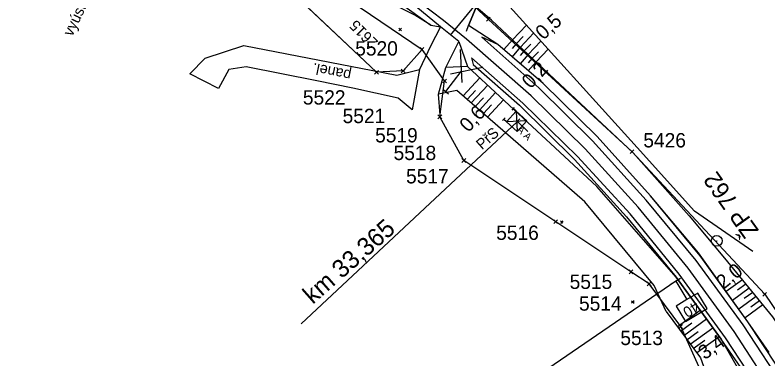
# Model space of a CAD drawing. Extents: x -805011 to -803920, y -1150790 to -1150234.
# Drawn here: x -804282.8 to -804177.7, y -1150562.3 to -1150514.3 of the extents above; entities that cross this region are included whole.
import ezdxf

# ---------------------------------------------------------------- set-up
doc = ezdxf.new("R2010")
doc.units = 0
for name, color, linetype in [('0381KM032-037P - Vrstva 1', 7, 'Continuous'), ('0381KM032-037P - Vrstva 4', 7, 'Continuous'), ('0381KM032-037P - Vrstva 43', 7, 'Continuous'), ('0381KM032-037P - Vrstva 48', 7, 'Continuous'), ('0381KM032-037P - Vrstva 49', 7, 'Continuous'), ('0381KM032-037P - Vrstva 5', 7, 'Continuous'), ('0381KM032-037P - Vrstva 51', 7, 'Continuous'), ('0381KM032-037P - Vrstva 55', 7, 'Continuous'), ('0381KM032-037P - Vrstva 57', 7, 'Continuous'), ('0381KM032-037P - Vrstva 6', 7, 'Continuous'), ('0381KM032-037P - Vrstva 7', 7, 'Continuous'), ('szdc - hran DP', 7, 'Continuous'), ('szdc - szdc_cislo', 7, 'Continuous'), ('szdc - szdc_krizek', 7, 'Continuous'), ('vyt_sit - ohrožené', 7, 'Continuous')]:
    doc.layers.add(name, color=color, linetype=linetype)

msp = doc.modelspace()

# ---------------------------------------------------------------- linework, layer by layer
at = {"layer": '0381KM032-037P - Vrstva 1'}
for points in [[(-804222.98, -1150515.09), (-804226.42, -1150512.48), (-804234.26, -1150506.83), (-804242.54, -1150501.49), (-804250.96, -1150496.61), (-804260.8, -1150491.55), (-804271.59, -1150486.76), (-804282.48, -1150482.69), (-804291.53, -1150479.85), (-804302.34, -1150477.08), (-804311.51, -1150475.27), (-804320.67, -1150473.88), (-804330.92, -1150472.81), (-804341.55, -1150472.27), (-804345.19, -1150472.22)], [(-804170.82, -1150577.3), (-804176.26, -1150567.85), (-804182.37, -1150558.45), (-804188.8, -1150549.63), (-804195.8, -1150541.09), (-804203.2, -1150532.98), (-804210.73, -1150525.57), (-804219.76, -1150517.68), (-804222.98, -1150515.09)]]:
    msp.add_lwpolyline(points, dxfattribs=at)
at = {"layer": '0381KM032-037P - Vrstva 4'}
for p, q in [((-804186.06, -1150473.54), (-804222.06, -1150517.12)), ((-804219.76, -1150517.68), (-804222.98, -1150515.09)), ((-804220.66, -1150519.13), (-804220.42, -1150523.73)), ((-804222, -1150522.51), (-804217.49, -1150521.57)), ((-804222.65, -1150524.98), (-804220.51, -1150522.21)), ((-804223.05, -1150524.67), (-804222.25, -1150525.29))]:
    msp.add_line(p, q, dxfattribs=at)
for points in [[(-804223.37, -1150515.97), (-804226.85, -1150513.1), (-804234.67, -1150507.48), (-804242.93, -1150502.16), (-804251.31, -1150497.29), (-804261.13, -1150492.25), (-804271.85, -1150487.49), (-804282.71, -1150483.42), (-804291.73, -1150480.59), (-804302.46, -1150477.85), (-804311.66, -1150476.01), (-804320.71, -1150474.65), (-804330.94, -1150473.58), (-804341.55, -1150473.05), (-804345.16, -1150472.99), (-804355.02, -1150473.16), (-804364.28, -1150473.69), (-804373.57, -1150474.51), (-804382.12, -1150475.46), (-804390.26, -1150476.46), (-804394.25, -1150476.96), (-804430.61, -1150481.56), (-804470.33, -1150486.56), (-804515.43, -1150492.3)], [(-804235.83, -1150507.71), (-804224.74, -1150515.72), (-804223.37, -1150515.97)], [(-804187.11, -1150547.91), (-804194.06, -1150539.52), (-804201.53, -1150531.26), (-804209.07, -1150523.88), (-804215.39, -1150518.4), (-804217.61, -1150517.41)], [(-804187.68, -1150548.56), (-804194.64, -1150540.13), (-804202.18, -1150531.87), (-804209.67, -1150524.48), (-804217.61, -1150517.41)], [(-804190.06, -1150550.44), (-804196.91, -1150542.06), (-804204.25, -1150534.03), (-804211.9, -1150526.62), (-804219.04, -1150520.28), (-804218.83, -1150521.2), (-804212.36, -1150526.9), (-804204.69, -1150534.44)], [(-804204.69, -1150534.44), (-804197.43, -1150542.44), (-804190.46, -1150550.87)], [(-804155.96, -1150604.81), (-804160.35, -1150595.07), (-804164.87, -1150585.5), (-804169.43, -1150576.62), (-804175.01, -1150566.82), (-804181.12, -1150557.55), (-804187.68, -1150548.56)], [(-804155.31, -1150604.52), (-804159.65, -1150594.76), (-804164.13, -1150585.17), (-804168.86, -1150576.08), (-804174.28, -1150566.45), (-804180.44, -1150557.11), (-804187.11, -1150547.91)], [(-804159.67, -1150606.25), (-804163.99, -1150596.78), (-804168.29, -1150587.2), (-804172.88, -1150578.5), (-804178.08, -1150568.91), (-804181.43, -1150563.5), (-804184.18, -1150559.55), (-804190.46, -1150550.87)], [(-804158.94, -1150605.89), (-804163.07, -1150596.41), (-804167.66, -1150586.77), (-804172.11, -1150577.99), (-804177.55, -1150568.56), (-804183.56, -1150559.32), (-804190.06, -1150550.44)]]:
    msp.add_lwpolyline(points, dxfattribs=at)
at = {"layer": '0381KM032-037P - Vrstva 48'}
for p, q in [((-804213.32, -1150517.78), (-804211.39, -1150515.72)), ((-804212.77, -1150518.3), (-804211.83, -1150517.29)), ((-804212.22, -1150518.81), (-804210.38, -1150516.84)), ((-804213.34, -1150517.77), (-804214.53, -1150519.14)), ((-804212.79, -1150518.28), (-804213.38, -1150518.96)), ((-804211.68, -1150519.32), (-804210.78, -1150518.36)), ((-804211.13, -1150519.83), (-804209.37, -1150517.95)), ((-804212.24, -1150518.79), (-804213.4, -1150520.12)), ((-804211.7, -1150519.3), (-804212.27, -1150519.96)), ((-804210.58, -1150520.35), (-804209.72, -1150519.43)), ((-804210.04, -1150520.86), (-804208.36, -1150519.07)), ((-804211.15, -1150519.82), (-804212.27, -1150521.11)), ((-804210.6, -1150520.33), (-804211.15, -1150520.97)), ((-804210.05, -1150520.84), (-804211.13, -1150522.09)), ((-804220.22, -1150525.59), (-804217.9, -1150523.08)), ((-804219.09, -1150526.57), (-804216.8, -1150524.1)), ((-804219.66, -1150526.08), (-804218.5, -1150524.83)), ((-804217.96, -1150527.56), (-804215.7, -1150525.12)), ((-804218.53, -1150527.07), (-804217.39, -1150525.84)), ((-804217.39, -1150528.05), (-804216.27, -1150526.84)), ((-804216.83, -1150528.54), (-804214.6, -1150526.14)), ((-804181.21, -1150551.27), (-804183.47, -1150552.89)), ((-804180.74, -1150551.85), (-804181.89, -1150552.67)), ((-804180.26, -1150552.43), (-804182.6, -1150554.11)), ((-804179.78, -1150553.01), (-804180.97, -1150553.86)), ((-804179.31, -1150553.59), (-804181.72, -1150555.33)), ((-804178.83, -1150554.17), (-804180.06, -1150555.05)), ((-804178.35, -1150554.75), (-804180.85, -1150556.54)), ((-804190.31, -1150557.81), (-804187.11, -1150555.5)), ((-804189.86, -1150558.41), (-804188.27, -1150557.26)), ((-804189.41, -1150559.01), (-804186.23, -1150556.71)), ((-804188.52, -1150560.22), (-804185.35, -1150557.93)), ((-804188.97, -1150559.62), (-804187.38, -1150558.47)), ((-804187.63, -1150561.43), (-804184.47, -1150559.14)), ((-804188.08, -1150560.82), (-804186.49, -1150559.68))]:
    msp.add_line(p, q, dxfattribs=at)
at = {"layer": '0381KM032-037P - Vrstva 49'}
for p, q in [((-804218.43, -1150513.19), (-804219.46, -1150515.79)), ((-804216.26, -1150515.03), (-804218.43, -1150513.19)), ((-804224.74, -1150515.72), (-804226.97, -1150514.32)), ((-804228.85, -1150516.15), (-804229.21, -1150516.51)), ((-804229.21, -1150516.15), (-804228.85, -1150516.51)), ((-804220.84, -1150517.99), (-804219.6, -1150521.51)), ((-804219.6, -1150521.51), (-804222.65, -1150521.62)), ((-804221.09, -1150524.83), (-804223.68, -1150525.36)), ((-804206.29, -1150543.01), (-804206.64, -1150543.37)), ((-804206.64, -1150543.01), (-804206.29, -1150543.36)), ((-804196.35, -1150554.16), (-804196.7, -1150554.52)), ((-804196.7, -1150554.16), (-804196.34, -1150554.52))]:
    msp.add_line(p, q, dxfattribs=at)
for points in [[(-804226.97, -1150514.32), (-804233.94, -1150510.78), (-804236.52, -1150508.57), (-804243.93, -1150503.82), (-804252.72, -1150498.82), (-804262.25, -1150494.6), (-804273.33, -1150489.4), (-804283.59, -1150485.01), (-804292.89, -1150482.47), (-804303.02, -1150479.68), (-804312.2, -1150478.16), (-804321.12, -1150476.62), (-804331.14, -1150475.24), (-804341.8, -1150475.06), (-804345.41, -1150474.87), (-804355.14, -1150475.34), (-804364.22, -1150475.73), (-804373.58, -1150476.33), (-804382.14, -1150477.38), (-804390.01, -1150478.23), (-804394.36, -1150478.78), (-804430.35, -1150482.91), (-804470.16, -1150488.05), (-804515.21, -1150493.93)], [(-804179.78, -1150547.3), (-804187.89, -1150541.65), (-804195.9, -1150532.8), (-804214.14, -1150512.69)], [(-804216.26, -1150515.03), (-804196.49, -1150533.54), (-804188.66, -1150542.31), (-804183.72, -1150548.22), (-804177, -1150556.4), (-804165.66, -1150573.06), (-804155.49, -1150590.5), (-804146.45, -1150604.86), (-804136.37, -1150622.31), (-804131.91, -1150629.82), (-804122.71, -1150645.64), (-804115.71, -1150666.79), (-804102.89, -1150677.06), (-804092.51, -1150687.92), (-804076.71, -1150692.97), (-804062.72, -1150701.97), (-804052.08, -1150706.52)], [(-804220.84, -1150517.99), (-804223.37, -1150515.97), (-804224.79, -1150518.63), (-804226.34, -1150521.9), (-804227.33, -1150527.53)], [(-804194.06, -1150539.52), (-804201.53, -1150531.26), (-804209.07, -1150523.88), (-804215.39, -1150518.4), (-804219.46, -1150515.79)], [(-804223.68, -1150525.36), (-804222.65, -1150521.62), (-804220.84, -1150517.99)], [(-804190.46, -1150550.87), (-804201.54, -1150538.22), (-804219.6, -1150521.51)], [(-804191.88, -1150555.68), (-804193.53, -1150552.03), (-804203.25, -1150540.38), (-804221.09, -1150524.83)], [(-804177.46, -1150561.39), (-804180.44, -1150557.11), (-804187.34, -1150547.5), (-804194.06, -1150539.52)], [(-804190.46, -1150550.87), (-804184.18, -1150559.55), (-804171.89, -1150581.01)], [(-804191.88, -1150555.68), (-804187.09, -1150562.15), (-804183.47, -1150572.06), (-804177.47, -1150586.83), (-804171.32, -1150602.68), (-804162.19, -1150629.63), (-804127.41, -1150694.05), (-804117.85, -1150694.76), (-804107.49, -1150702.04), (-804103.03, -1150704.73), (-804070.42, -1150728.33), (-804053.81, -1150732.63), (-804001.62, -1150732.39)]]:
    msp.add_lwpolyline(points, dxfattribs=at)
at = {"layer": '0381KM032-037P - Vrstva 5'}
for p, q in [((-804189.88, -1150551.06), (-804191.16, -1150551.84)), ((-804190.52, -1150551.45), (-804225.17, -1150575.08))]:
    msp.add_line(p, q, dxfattribs=at)
msp.add_lwpolyline([(-804190.52, -1150551.45), (-804188.96, -1150554.01), (-804190.45, -1150554.92), (-804189.15, -1150557.05), (-804186.16, -1150555.23), (-804187.46, -1150553.1), (-804188.96, -1150554.01)], dxfattribs=at)
at = {"layer": '0381KM032-037P - Vrstva 51'}
for points in [[(-804219.78, -1150516.58), (-804219.46, -1150515.79), (-804218.43, -1150513.19), (-804217.51, -1150509.9), (-804216.47, -1150506.86)], [(-804223.37, -1150515.97), (-804224.79, -1150518.63), (-804226.34, -1150521.9), (-804227.33, -1150527.53)], [(-804223.45, -1150528.25), (-804223.68, -1150525.36), (-804222.65, -1150521.62), (-804220.84, -1150517.99)], [(-804227.33, -1150527.53), (-804229.32, -1150525.92), (-804235.62, -1150524.51), (-804240.66, -1150523.49), (-804250.54, -1150521.55), (-804252.94, -1150521.92), (-804254.39, -1150524.56), (-804258.4, -1150522.49), (-804256.28, -1150520.34), (-804250.86, -1150518.54), (-804232.85, -1150522.07), (-804229.47, -1150522.71), (-804226.34, -1150521.9)]]:
    msp.add_lwpolyline(points, dxfattribs=at)
at = {"layer": '0381KM032-037P - Vrstva 55'}
msp.add_lwpolyline([(-804254.35, -1150501.48), (-804247.48, -1150504.53), (-804225.97, -1150519.11), (-804228.6, -1150522.11), (-804232.32, -1150522.3)], close=True, dxfattribs=at)
at = {"layer": '0381KM032-037P - Vrstva 6'}
for p, q in [((-804212.29, -1150528.81), (-804212.99, -1150529.53)), ((-804212.64, -1150529.17), (-804242.83, -1150557.41)), ((-804211.21, -1150530.54), (-804212.64, -1150529.17))]:
    msp.add_line(p, q, dxfattribs=at)
at = {"layer": '0381KM032-037P - Vrstva 7'}
for p, q in [((-804212.83, -1150527.71), (-804214.18, -1150529.19)), ((-804213.37, -1150527.56), (-804213.03, -1150527.19)), ((-804212.83, -1150527.71), (-804213.2, -1150527.38)), ((-804212.83, -1150527.71), (-804211.35, -1150529.06)), ((-804212.83, -1150527.71), (-804212.7, -1150530.54)), ((-804214.71, -1150529.04), (-804214.38, -1150528.67)), ((-804214.18, -1150529.19), (-804214.55, -1150528.86)), ((-804211.35, -1150529.06), (-804214.18, -1150529.19)), ((-804214.18, -1150529.19), (-804212.7, -1150530.54)), ((-804211.35, -1150529.06), (-804212.7, -1150530.54))]:
    msp.add_line(p, q, dxfattribs=at)
at = {"layer": 'szdc - hran DP'}
for p, q in [((-804232.32, -1150522.3), (-804254.35, -1150501.48)), ((-804221.41, -1150510.55), (-804216.71, -1150514.88)), ((-804216.71, -1150514.88), (-804196.65, -1150533.37)), ((-804225.97, -1150519.11), (-804228.6, -1150522.11)), ((-804222.81, -1150523.51), (-804225.97, -1150519.11)), ((-804228.6, -1150522.11), (-804232.32, -1150522.3)), ((-804223.47, -1150528.51), (-804222.81, -1150523.51)), ((-804220.13, -1150534.61), (-804223.47, -1150528.51)), ((-804196.65, -1150533.37), (-804178.11, -1150553.27)), ((-804207.3, -1150543.14), (-804220.13, -1150534.61)), ((-804196.79, -1150550.13), (-804207.3, -1150543.14)), ((-804194.25, -1150551.81), (-804196.79, -1150550.13)), ((-804189.84, -1150557.76), (-804194.25, -1150551.81)), ((-804178.11, -1150553.27), (-804167.37, -1150569.11)), ((-804182.55, -1150573.8), (-804189.84, -1150557.76))]:
    msp.add_line(p, q, dxfattribs=at)
at = {"layer": 'szdc - szdc_krizek'}
for p, q in [((-804216.45, -1150515.15), (-804216.98, -1150514.61)), ((-804216.98, -1150515.15), (-804216.45, -1150514.61)), ((-804225.71, -1150519.38), (-804226.24, -1150518.84)), ((-804226.24, -1150519.38), (-804225.71, -1150518.84)), ((-804232.06, -1150522.56), (-804232.59, -1150522.03)), ((-804232.59, -1150522.56), (-804232.06, -1150522.03)), ((-804228.33, -1150522.38), (-804228.87, -1150521.84)), ((-804228.87, -1150522.38), (-804228.33, -1150521.84)), ((-804222.55, -1150523.78), (-804223.08, -1150523.25)), ((-804223.08, -1150523.78), (-804222.55, -1150523.25)), ((-804223.21, -1150528.78), (-804223.74, -1150528.25)), ((-804223.74, -1150528.78), (-804223.21, -1150528.25)), ((-804196.39, -1150533.64), (-804196.92, -1150533.1)), ((-804196.92, -1150533.64), (-804196.39, -1150533.1)), ((-804219.86, -1150534.88), (-804220.4, -1150534.34)), ((-804220.4, -1150534.88), (-804219.86, -1150534.34)), ((-804207.04, -1150543.41), (-804207.57, -1150542.88)), ((-804207.57, -1150543.41), (-804207.04, -1150542.88)), ((-804196.53, -1150550.4), (-804197.06, -1150549.86)), ((-804197.06, -1150550.4), (-804196.53, -1150549.86)), ((-804193.98, -1150552.07), (-804194.52, -1150551.54)), ((-804194.52, -1150552.07), (-804193.98, -1150551.54)), ((-804177.84, -1150553.53), (-804178.38, -1150553.01)), ((-804178.38, -1150553.53), (-804177.84, -1150553.01)), ((-804189.58, -1150558.03), (-804190.11, -1150557.5)), ((-804190.11, -1150558.03), (-804189.58, -1150557.5))]:
    msp.add_line(p, q, dxfattribs=at)
at = {"layer": 'vyt_sit - ohrožené'}
msp.add_line((-804184.86, -1150545.81), (-804184.76, -1150545.81), dxfattribs=at)
msp.add_circle((-804184.81, -1150545.81), 0.756, dxfattribs=at)

# ---------------------------------------------------------------- texts
at = {"layer": '0381KM032-037P - Vrstva 43'}
msp.add_text('vyústění trubního propustku', height=1.5, rotation=64.5558, dxfattribs=at).set_placement((-804274.83, -1150517.39))
at = {"layer": '0381KM032-037P - Vrstva 48'}
for s, rotation, p in [('0,5', 42.198, (-804209.02, -1150517.88)), ('0,2', 46.8794, (-804210.79, -1150524.7)), ('0,6', 47.212, (-804219.48, -1150530.78)), ('2,0', 39.3887, (-804183.86, -1150552.67)), ('3,4', 35.3381, (-804186.49, -1150562.48))]:
    msp.add_text(s, height=2, rotation=rotation, dxfattribs=at).set_placement(p)
at = {"layer": '0381KM032-037P - Vrstva 5'}
msp.add_text('40', height=1.5, rotation=211.3344, dxfattribs=at).set_placement((-804187.79, -1150554.17))
at = {"layer": '0381KM032-037P - Vrstva 51'}
msp.add_text('panel.', height=1.5, rotation=168.559, dxfattribs=at).set_placement((-804235.76, -1150522.06))
at = {"layer": '0381KM032-037P - Vrstva 57'}
msp.add_text('2615', height=1.5, rotation=135.0206, dxfattribs=at).set_placement((-804232.02, -1150518.03))
at = {"layer": '0381KM032-037P - Vrstva 6'}
for s, height, rotation, p in [('  A A ', 1, 316.3444, (-804213.33, -1150529.89)), ('PřS', 1.5, 41.3444, (-804217.6, -1150533.18)), ('km 33,365', 2.5, 41.3444, (-804241.24, -1150554.74))]:
    msp.add_text(s, height=height, rotation=rotation, dxfattribs=at).set_placement(p)
at = {"layer": 'szdc - szdc_cislo'}
for s, p in [('5520', (-804235.3, -1150519.96)), ('5522', (-804242.61, -1150526.8)), ('5521', (-804237.06, -1150529.39)), ('5519', (-804232.52, -1150532.08)), ('5426', (-804195.06, -1150532.78)), ('5518', (-804229.94, -1150534.54)), ('5517', (-804228.2, -1150537.8)), ('5516', (-804215.61, -1150545.68)), ('5515', (-804205.35, -1150552.52)), ('5514', (-804204.04, -1150555.55)), ('5513', (-804198.27, -1150560.35))]:
    msp.add_text(s, height=2, dxfattribs=at).set_placement(p)
at = {"layer": 'vyt_sit - ohrožené'}
msp.add_text('ŽP 762', height=2.4, rotation=125.4386, dxfattribs=at).set_placement((-804178.85, -1150544.36))

doc.saveas('drawing.dxf')
